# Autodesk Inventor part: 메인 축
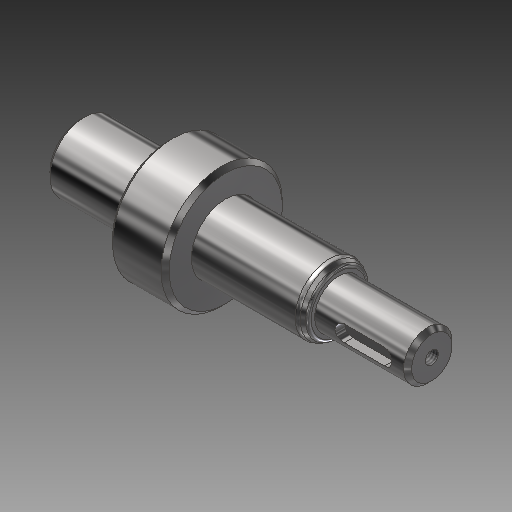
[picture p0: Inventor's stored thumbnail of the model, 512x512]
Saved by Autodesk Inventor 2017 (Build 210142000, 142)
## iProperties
Created: 2016-04
Part Number: 메인 축
Document SubType Name: Modeling
Designer: mdu
Density: 7.86 g/cm^3
Mass: 230.24 g
Surface Area: 74.3518 cm^2
Volume: 29.2926 cm^3
Material: 강철, 연강
Appearance: 반광택
Author: mdu
Revision Number: 1
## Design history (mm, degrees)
sketch "스케치1"
  geometry: L1 (10.497, -57.5)-(97.497, -57.5); L2 (10.497, -66)-(32.497, -66); L3 (32.497, -72.5)-(46.5, -72.5); L4 (46.5, -66)-(74.497, -66); L5 (97.497, -63.5)-(97.497, -57.5); L6 (10.497, -66)-(10.497, -57.5); L7 (46.5, -69.749)-(46.5, -45.251) reference; L8 (46.5, -72.5)-(46.5, -66); L9 (32.497, -72.5)-(32.497, -66); L10 (32.497, -35)-(32.497, -80) reference; L11 (97.497, -63.5)-(74.497, -63.5); L12 (74.497, -63.5)-(74.497, -66); 3 further points
  constraints: 20 end point, 4 perpendicular, 3 point on line, 2 parallel, 1 collinear, 1 horizontal, 1 midpoint
  dimensions: "d0" = 17 diameter of L4 L1; "d1" = 30 diameter of L3 L1; "d2" = 22 distance of L2.start L2.end; "d5" = 17 diameter of L2 L1; "d19" = 65 distance between parallel lines of L5 L9; "d21" = 50.99692 distance between parallel lines of L5 L8 (derived); "d22" = 23 distance between parallel lines of L5 L12; "d23" = 12 diameter of L11 L1
revolve "회전1" sketch "스케치1" stored, may be unused: angle "d4" = 90 deg
chamfer "모따기1" distance "d6" = 1; stored, may be unused: second distance "d7" = 2, angle "d8" = 45 deg
node "작업 평면1"
sketch "스케치2"
  geometry: L1 (10.497, -65)-(10.497, -50) reference; L2 (16.997, -55)-(25.997, -55); L3 (25.997, -60)-(16.997, -60); A1 r 2.5 centre (25.997, -57.5) between (25.997, -60) and (25.997, -55); A2 r 2.5 centre (16.997, -57.5) between (16.997, -55) and (16.997, -60); 2 further points
  constraints: 4 end point, 4 point on circle, 4 tangent, 2 centre point, 1 horizontal alignment, 1 midpoint, 1 parallel, 1 perpendicular
  dimensions: "d9" = 5 distance between parallel lines of L3 L2; "d10" = 14 dimension on A1 A2; "d11" = 4 distance edge to line of A2 L1
extrude "돌출1" cut sketch "스케치2" distance "d12" = 3; taper "d13" = 0 deg
node "작업 평면2"
sketch "스케치3"
  geometry: L1 (91.497, -55.5)-(81.497, -55.5); L2 (81.497, -59.5)-(91.497, -59.5); L3 (97.497, -52.5)-(97.497, -62.5) reference; A1 r 2 centre (81.497, -57.5) between (81.497, -55.5) and (81.497, -59.5); A2 r 2 centre (91.497, -57.5) between (91.497, -59.5) and (91.497, -55.5); 4 further points
  constraints: 4 end point, 4 point on circle, 4 tangent, 2 centre point, 2 horizontal, 2 point on line, 1 horizontal alignment, 1 midpoint, 1 vertical alignment
  dimensions: "d32" = 14 dimension on A2 A1; "d34" = 4 distance edge to line of A2 L3; "d35" = 4 distance between parallel lines of L2 L1
extrude "돌출2" cut sketch "스케치3" distance "d16" = 2.5; taper "d17" = 0 deg
sketch "스케치4"
  geometry: L1 (74.497, -50.05)-(72.678, -49); L2 (74.497, -49)-(46.5, -49) reference; L3 (74.497, -49)-(74.497, -66) reference; L4 (74.497, -66)-(46.5, -66) reference; L5 (74.497, -57.5)-(60.711, -57.5); 1 further point
  constraints: 4 end point, 2 point on line, 1 midpoint, 1 parallel
  dimensions: "d24" = 14.9 diameter of L1.start L5; "d26" = 30 deg angle of L2 L1
revolve "회전2" sketch "스케치4" stored, may be unused: angle "d28" = 90 deg
fillet "모깎기1" dims "d29" = 1
fillet "모깎기2" dims "d30" = 2
hole "구멍1" diameter "d38" = 3.242; stored, may be unused: countersink angle "d42" = 90 deg, drill point angle "d44" = 118 deg; dims "d39" = 8, "d40" = 4, "d41" = 2, "d43" = 10, "d45" = 10, "d46" = 10
node "솔리드1"
node "참조4"
node "참조5"
other parameters: "d20" = 6, "d47" = -8.5
